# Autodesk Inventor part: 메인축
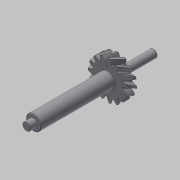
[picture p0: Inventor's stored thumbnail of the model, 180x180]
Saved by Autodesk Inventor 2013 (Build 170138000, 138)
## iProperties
Created: 2016-12
Part Number: 메인축
Material: 강철, 탄소
Document SubType Name: Modeling
Designer: mduedu
Categories: <?xml version="1.0" encoding="UTF-16"?> <MemberInstance><Categories><FamilyTemplate><FamilyTemplateParameter ValueType="xs:double" Id="1" ObjectReferenceKey="da
Density: 7.87 g/cm^3
Mass: 199.41 g
Surface Area: 86.9446 cm^2
Volume: 25.338 cm^3
Author: mduedu
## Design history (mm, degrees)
sketch "Sketch1"
  geometry: C1 r 19.321 at (0, 0)
  constraints: 1 centre point
  dimensions: "d0" = 38.64102 diameter of C1 (= da_da)
extrude "Extrusion1" new body sketch "Sketch1" distance "d1" = 10 (= da_b); taper "d2" = 0 deg
workplane "Work Plane2"
sketch "Sketch2"
  geometry: C1 r 19.321 at (0, 0) reference; C2 r 17.321 at (0, 0)
  constraints: 1 centre point, 1 coincident
  dimensions: "d3" = 34.64102 diameter of C2 (= da_dw)
feature "피치 지름" sketch "Sketch2" dims "d4" = 10, "d5" = 0
workplane "Work Plane8"
workplane "Work Plane9"
feature "스퍼 기어" dims "da_b" = 10, "da_d" = 34.64102, "da_aw" = 43.87862, "da_da" = 38.64102, "da_df" = 29.64102, "da_dw" = 34.64102, angle "da_beta" = 30 deg, "da_lefttooth" = 0, "da_righttooth" = 10
sketch "스케치3"
  geometry: C1 r 7.5 at (0, 0); 1 further point
  constraints: 1 centre point, 1 coincident
  dimensions: "d49" = 15 diameter of C1
extrude "돌출2" join sketch "스케치3" distance "d50" = 74; taper "d51" = 0 deg
sketch "스케치4"
  geometry: C1 r 4 at (0, 0); 1 further point
  constraints: 1 centre point, 1 coincident
  dimensions: "d52" = 8 diameter of C1
extrude "돌출3" join sketch "스케치4" distance "d53" = 7; taper "d54" = 0 deg
sketch "스케치5"
  geometry: C1 r 7.5 at (0, 0) reference; 1 further point
extrude "돌출4" join sketch "스케치5" distance "d55" = 6; taper "d56" = 0 deg
sketch "스케치6"
  geometry: C1 r 4 at (0, 0); 1 further point
  constraints: 1 centre point, 1 coincident
  dimensions: "d57" = 8 diameter of C1
extrude "돌출5" join sketch "스케치6" distance "d58" = 30; taper "d59" = 0 deg
chamfer "모따기1" distance "d60" = 0.5; stored, may be unused: second distance "d61" = 2, angle "d62" = 45 deg
fillet "모깎기1" dims "d63" = 0.5
sketch "스케치7" dims "d64" = 25
  geometry: C1 r 1 at (0, 12.5); 2 further points
  constraints: 2 vertical alignment, 1 centre point, 1 coincident, 2 other
  dimensions: "d65" = 2 diameter of C1
extrude "돌출6" join sketch "스케치7" distance "d66" = 0.5; taper "d67" = 0 deg
body "Solid1"
body "Srf1"
other parameters: "d16" = 43.87862 (= da_aw), "d17" = 0, "d34" = 12 deg (computed from da_z), "d39" = 0, "d41" = 0, "d43" = 43.87862 (= da_aw), "d46" = 43.87862 (= da_aw), "d47" = 0, "d48" = 0
